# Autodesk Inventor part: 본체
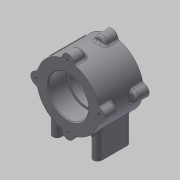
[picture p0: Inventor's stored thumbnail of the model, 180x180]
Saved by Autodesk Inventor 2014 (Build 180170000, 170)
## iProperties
Created: 2015-03
Part Number: 본체
Material: Generic
Document SubType Name: Modeling
Designer: MYHOME
Density: 1 g/cm^3
Appearance: Default
Author: MYHOME
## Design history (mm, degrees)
sketch "스케치2"
  geometry: C1 r 37 at (0, 0); 1 further point
  constraints: 1 centre point, 1 coincident
  dimensions: "d0" = 74 diameter of C1
extrude "돌출1" new body sketch "스케치2" stored distance "d1" = 52; taper "d2" = 0 deg
sketch "스케치3"
  geometry: C1 r 37 at (0, 0) reference; C2 r 23.5 at (0, 0)
  constraints: 1 centre point, 1 coincident
  dimensions: "d3" = 47 diameter of C2
extrude "돌출2" cut sketch "스케치3" distance "d4" = 22; taper "d5" = 0 deg
sketch "스케치4"
  geometry: C1 r 23.5 at (0, 0) reference; C2 r 7 at (0, 37); C3 r 7 at (-37, 0); C4 r 7 at (0, -37); C5 r 7 at (37, 0); A1 r 37 centre (0, 0) between (0, 37) and (-37, 0) reference
  constraints: 4 centre point, 4 point on circle, 2 horizontal alignment, 2 vertical alignment
  dimensions: "d6" = 14 diameter of C3; "d7" = 14 diameter of C4; "d8" = 14 diameter of C5; "d9" = 14 diameter of C2
extrude "돌출3" join sketch "스케치4" distance "d10" = 15; taper "d11" = 0 deg
sketch "스케치5"
  geometry: A1 r 37 centre (0, 0) between (36.338, 6.969) and (6.969, 36.338) reference; A2 r 7 centre (0, 37) between (6.969, 36.338) and (-6.969, 36.338) reference; A3 r 7 centre (-37, 0) between (-36.338, 6.969) and (-36.338, -6.969) reference; A4 r 7 centre (0, -37) between (-6.969, -36.338) and (6.969, -36.338) reference; A5 r 7 centre (37, 0) between (36.338, -6.969) and (36.338, 6.969) reference; 4 further points
  constraints: 4 coincident, 2 horizontal alignment, 2 vertical alignment
hole "구멍1" sketch "스케치5" at (0, 37), (0, -37), (37, 0), (-37, 0) diameter "d12" = 3.242; stored, may be unused: countersink angle "d16" = 90 deg, drill point angle "d18" = 118 deg; dims "d13" = 8, "d14" = 4, "d15" = 2, "d17" = 11
sketch "스케치6"
  geometry: C1 r 23.5 at (0, 0) reference; C2 r 21 at (0, 0)
  constraints: 1 centre point, 1 coincident
  dimensions: "d19" = 42 diameter of C2
extrude "돌출4" cut sketch "스케치6" distance "d20" = 8; taper "d21" = 0 deg
sketch "스케치7"
  geometry: L1 (-29, -22.978)-(-29, -56); L2 (-29, -56)-(-19, -56); L3 (-19, -56)-(-19, -31.749); A1 r 37 centre (0, 0) between (-36.338, -6.969) and (-6.969, -36.338) reference; 1 further point
  constraints: 6 end point, 2 point on circle, 1 parallel, 1 perpendicular, 1 vertical
  dimensions: "d22" = 56 distance from line of L2 point (0, 0); "d23" = 29 distance from line of L1 point (0, 0); "d24" = 10 distance of L1.end L2.end
extrude "돌출5" join sketch "스케치7" stored distance "d25" = 40; taper "d26" = 0 deg
sketch "스케치8"
  geometry: L1 (10, 0)-(10, -40) reference; L2 (0, 0)-(10, 0) reference; L3 (10, -40)-(0, -40) reference; 3 further points
  dimensions: "d27" = 5 distance from line of L1 point (5, -5); "d28" = 5 distance from line of L1 point (5, -35); "d29" = 5 distance from line of L3 point (5, -35); "d30" = 5 distance from line of L2 point (5, -5)
hole "구멍2" sketch "스케치8" at (5, -5), (5, -35) diameter "d31" = 4.134; stored, may be unused: countersink angle "d35" = 90 deg, drill point angle "d37" = 118 deg; dims "d32" = 6, "d33" = 4, "d34" = 2, "d36" = 8
sketch "스케치9"
  geometry: L1 (0, 0)-(0, 37); L2 (0, 0)-(26.163, 26.163); A1 r 37 centre (0, 0) between (36.338, 6.969) and (6.969, 36.338) reference; 2 further points
  constraints: 4 end point, 2 point on circle, 1 coincident, 1 vertical
  dimensions: "d38" = 45 deg angle of L2 L1
node "작업 평면1"
sketch "스케치10"
  geometry: L1 (-26, 20.767)-(-26, -20.767) reference; 2 further points
  constraints: 1 coincident, 1 other
  dimensions: "d39" = 26 distance from line of L1 point (0, 0)
feature "엠보싱1" sketch "스케치10" dims "d40" = 0.5, "d41" = 0
chamfer "모따기1" distance "d42" = 1; stored, may be unused: second distance "d43" = 2, angle "d44" = 45 deg
fillet "모깎기1" dims "d45" = 5
fillet "모깎기2" dims "d46" = 3
fillet "모깎기3" dims "d47" = 3
fillet "모깎기4" dims "d48" = 3
fillet "모깎기5" dims "d49" = 0.3
node "솔리드1"
mirror "대칭1"
mirror "대칭2"
